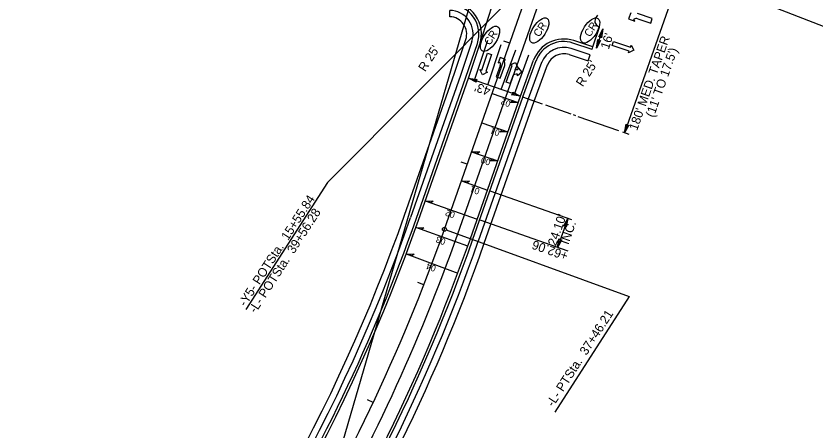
# Model space of a CAD drawing. Extents: x 1974386 to 1979988, y 776712 to 784860.
# Drawn here: x 1976973 to 1977598, y 780494 to 780818 of the extents above; entities that cross this region are included whole.
import ezdxf

# ---------------------------------------------------------------- set-up
doc = ezdxf.new("R2010")
doc.units = 0
for name, color, linetype in [('Prop Conc 2ft 6in Curb and Gutter', 7, 'Continuous'), ('Prop Conc 4in Sidewalk', 7, 'Continuous'), ('Prop Dimension', 7, 'Continuous'), ('Prop Dimension Text', 7, 'Continuous'), ('Prop EOT', 7, 'Continuous'), ('Prop Horizontal Alignment', 7, 'Continuous'), ('Prop Horizontal Alignment Station Label', 7, 'Continuous'), ('Prop Horizontal Alignment Tick Small', 7, 'Continuous'), ('Prop Lane Arrow CELL', 7, 'Continuous'), ('Prop Lane Lines', 7, 'Continuous'), ('Prop Superelevation  Arrow CELL', 7, 'Continuous'), ('Prop Superelevation Label', 7, 'Continuous'), ('Prop Terminator CELL', 7, 'Continuous'), ('Prop WCC CELL', 7, 'Continuous'), ('Scratch_Level_2', 7, 'Continuous'), ('Scratch_Level_3', 7, 'Continuous'), ('Sheet Layout Plan Border', 7, 'Continuous')]:
    doc.layers.add(name, color=color, linetype=linetype)

msp = doc.modelspace()

# ---------------------------------------------------------------- linework, layer by layer
at = {"layer": 'Prop Conc 2ft 6in Curb and Gutter'}
for p, q in [((1977423.02, 780791.58), (1977408.13, 780796.51)), ((1977324.63, 780769.91), (1977333.5, 780796.19)), ((1977423.02, 780791.58), (1977423.65, 780793.48)), ((1977369.03, 780754.48), (1977379.43, 780782.92)), ((1977285.65, 780659.07), (1977324.64, 780769.93)), ((1977329.99, 780643.48), (1977368.97, 780754.34))]:
    msp.add_line(p, q, dxfattribs=at)
for centre, radius, start, end in [((1977311.71, 780803.55), 23, 341.34263, 89.03553), ((1977400.9, 780774.68), 23, 71.68278, 159.91031), ((1975987.1, 781115.69), 1376.5, 328.18457, 340.62647), ((1975987.1, 781115.69), 1423.5, 326.24911, 340.62647)]:
    msp.add_arc(centre, radius, start, end, dxfattribs=at)
at = {"layer": 'Prop Conc 4in Sidewalk'}
for p, q in [((1977311.94, 780817.04), (1977312.02, 780822.04)), ((1977311.94, 780817.04), (1977311.98, 780819.54)), ((1977315.67, 780773.08), (1977324.5, 780799.23)), ((1977329.24, 780797.63), (1977320.36, 780771.35)), ((1977421.61, 780787.31), (1977406.72, 780792.24)), ((1977405.14, 780787.49), (1977420.04, 780782.56)), ((1977420.04, 780782.56), (1977421.61, 780787.31)), ((1977383.66, 780781.38), (1977373.24, 780752.91)), ((1977377.94, 780751.19), (1977388.35, 780779.66)), ((1977276.69, 780662.22), (1977315.67, 780773.08)), ((1977320.36, 780771.35), (1977281.41, 780660.56)), ((1977373.22, 780752.85), (1977334.24, 780641.98)), ((1977338.95, 780640.33), (1977377.94, 780751.19))]:
    msp.add_line(p, q, dxfattribs=at)
for centre, radius, start, end in [((1977311.71, 780803.55), 18.5, 341.34263, 89.03553), ((1977311.71, 780803.55), 13.5, 341.34263, 89.03553), ((1977400.9, 780774.68), 18.5, 71.68278, 159.91031), ((1977400.9, 780774.68), 13.5, 71.68278, 159.91031), ((1975987.1, 781115.69), 1367, 320.45193, 340.62647), ((1975987.1, 781115.69), 1372, 320.5086, 340.62647), ((1975987.1, 781115.69), 1428, 326.24911, 340.62647), ((1975987.1, 781115.69), 1433, 326.24911, 340.62647)]:
    msp.add_arc(centre, radius, start, end, dxfattribs=at)
at = {"layer": 'Prop Dimension'}
for p, q in [((1977508.17, 780896.2), (1977448.46, 780726.39)), ((1977426.51, 780792.53), (1977431.47, 780807.53)), ((1977367.09, 780755), (1977326.52, 780769.27)), ((1977384.39, 780748.92), (1977369.13, 780754.28)), ((1977406.69, 780741.08), (1977386.92, 780748.03)), ((1977410.43, 780739.76), (1977408.57, 780740.42)), ((1977443.97, 780727.97), (1977412.29, 780739.11)), ((1977451.87, 780725.19), (1977446.99, 780726.91)), ((1977407.19, 780658.68), (1977343.62, 780681.04)), ((1977404.05, 780659.79), (1977396.05, 780637.05)), ((1977404.49, 780634.09), (1977335.71, 780658.27))]:
    msp.add_line(p, q, dxfattribs=at)
at = {"layer": 'Prop EOT'}
for p, q in [((1977425.43, 780812.69), (1977425.62, 780815.57)), ((1977425.62, 780815.57), (1977427.56, 780818.27)), ((1977423.65, 780793.48), (1977428.77, 780808.93)), ((1977427.32, 780809.61), (1977425.43, 780812.69)), ((1977423.65, 780793.48), (1977408.76, 780798.41)), ((1977326.52, 780769.27), (1977335.4, 780795.55)), ((1977367.14, 780755.14), (1977377.42, 780783.26)), ((1977287.54, 780658.4), (1977326.52, 780769.27)), ((1977328.1, 780644.14), (1977367.09, 780755))]:
    msp.add_line(p, q, dxfattribs=at)
msp.add_lwpolyline([(1977428.77, 780808.93), (1977428.16, 780809.13), (1977427.32, 780809.61)], dxfattribs=at)
for centre, radius, start, end in [((1977311.71, 780803.55), 25, 341.34263, 89.03553), ((1977400.9, 780774.68), 25, 71.68278, 159.91031), ((1975987.1, 781115.69), 1378.5, 320.50095, 340.62647), ((1975987.1, 781115.69), 1421.5, 326.24911, 340.61773)]:
    msp.add_arc(centre, radius, start, end, dxfattribs=at)
at = {"layer": 'Prop Horizontal Alignment'}
msp.add_line((1977307.82, 780651.27), (1977457.11, 781075.82), dxfattribs=at)
msp.add_arc((1975987.1, 781115.69), 1400, 315.73946, 340.62647, dxfattribs=at)
at = {"layer": 'Prop Horizontal Alignment Station Label'}
for p, q in [((1977376.45, 780848.38), (1977216.45, 780687.69)), ((1977216.45, 780687.69), (1977152.74, 780588.6)), ((1977309.24, 780650.77), (1977451.88, 780598.87)), ((1977451.88, 780598.87), (1977393.85, 780508.64))]:
    msp.add_line(p, q, dxfattribs=at)
msp.add_circle((1977307.82, 780651.27), 1.5, dxfattribs=at)
at = {"layer": 'Prop Horizontal Alignment Tick Small'}
for p, q in [((1977358.84, 780796.36), (1977354.12, 780798.01)), ((1977325.67, 780702.02), (1977320.95, 780703.68)), ((1977291.78, 780607.94), (1977287.12, 780609.75)), ((1977252.21, 780516.12), (1977247.7, 780518.27))]:
    msp.add_line(p, q, dxfattribs=at)
at = {"layer": 'Prop Lane Arrow CELL'}
for p, q in [((1977453.25, 780820.12), (1977451.56, 780815.35)), ((1977451.56, 780815.35), (1977456.45, 780813.63)), ((1977456.45, 780813.63), (1977455.69, 780815.16)), ((1977470.02, 780815.7), (1977458.53, 780819.6)), ((1977458.84, 780815.49), (1977468.8, 780812.11)), ((1977468.8, 780812.11), (1977470.02, 780815.7)), ((1977438.76, 780794.66), (1977439.79, 780797.8)), ((1977439.79, 780797.8), (1977453.09, 780793.43)), ((1977452.06, 780790.3), (1977438.76, 780794.66)), ((1977455.58, 780790.93), (1977451.59, 780788.87)), ((1977451.59, 780788.87), (1977452.06, 780790.3)), ((1977453.09, 780793.43), (1977453.56, 780794.86)), ((1977453.56, 780794.86), (1977455.58, 780790.93)), ((1977336.96, 780775.35), (1977341.48, 780788.6)), ((1977344.61, 780787.54), (1977340.09, 780774.29)), ((1977341.48, 780788.6), (1977344.61, 780787.54)), ((1977351.29, 780785.21), (1977349.72, 780780.99)), ((1977355.41, 780783.68), (1977351.29, 780785.21)), ((1977351.31, 780778.89), (1977348.22, 780770.27)), ((1977349.72, 780780.99), (1977351.07, 780781.63)), ((1977351.33, 780769.16), (1977354.88, 780779.09)), ((1977354.07, 780783.05), (1977355.41, 780783.68)), ((1977356.06, 780766.05), (1977360.62, 780779.08)), ((1977359.2, 780779.57), (1977363.2, 780781.46)), ((1977360.62, 780779.08), (1977359.2, 780779.57)), ((1977363.73, 780777.99), (1977362.79, 780775.3)), ((1977363.2, 780781.46), (1977365.15, 780777.49)), ((1977365.15, 780777.49), (1977363.73, 780777.99)), ((1977337.55, 780771.82), (1977335.54, 780775.84)), ((1977335.54, 780775.84), (1977336.96, 780775.35)), ((1977341.5, 780773.8), (1977337.55, 780771.82)), ((1977340.09, 780774.29), (1977341.5, 780773.8)), ((1977368.15, 780773.8), (1977364.8, 780770.89)), ((1977364.8, 780770.89), (1977364.88, 780772.34)), ((1977365.14, 780775.64), (1977365.24, 780777.14)), ((1977365.24, 780777.14), (1977368.15, 780773.8)), ((1977348.22, 780770.27), (1977351.33, 780769.16)), ((1977359.18, 780764.96), (1977356.06, 780766.05)), ((1977361.31, 780771.05), (1977359.18, 780764.96))]:
    msp.add_line(p, q, dxfattribs=at)
for centre, radius, start, end in [((1977457.62, 780811.95), 3.77, 71.25132, 120.90949), ((1977348.24, 780780), 3.27, 340.30395, 29.96213), ((1977349.74, 780780.09), 5.25, 348.98002, 34.29172), ((1977363.4, 780769.64), 2.52, 109.80631, 146.11831), ((1977364.3, 780767.94), 4.43, 82.44284, 113.2964), ((1977364.54, 780771.24), 4.43, 82.32403, 113.20263)]:
    msp.add_arc(centre, radius, start, end, dxfattribs=at)
at = {"layer": 'Prop Lane Lines'}
for p, q in [((1977331.24, 780767.62), (1977341.8, 780798.87)), ((1977341.62, 780763.96), (1977352.01, 780795.31)), ((1977351.99, 780760.31), (1977363.47, 780791.16)), ((1977362.38, 780756.67), (1977373.63, 780787.45))]:
    msp.add_line(p, q, dxfattribs=at)
at = {"layer": 'Prop Superelevation  Arrow CELL'}
for p, q in [((1977345.06, 780757.17), (1977365.34, 780750.04)), ((1977337.06, 780734.43), (1977357.35, 780727.3)), ((1977329.07, 780711.7), (1977349.35, 780704.57)), ((1977321.08, 780688.96), (1977341.36, 780681.83)), ((1977292.8, 780673.36), (1977333.36, 780659.09)), ((1977325.98, 780638.15), (1977285.48, 780652.6)), ((1977278, 780632.14), (1977318.27, 780617.06))]:
    msp.add_line(p, q, dxfattribs=at)
for points in [[(1977365.34, 780750.04), (1977359.02, 780750.14), (1977360.98, 780751.57)], [(1977357.35, 780727.3), (1977351.02, 780727.4), (1977352.98, 780728.83)], [(1977329.07, 780711.7), (1977335.39, 780711.59), (1977333.43, 780710.16)], [(1977349.35, 780704.57), (1977343.03, 780704.67), (1977344.99, 780706.1)], [(1977321.08, 780688.96), (1977327.4, 780688.86), (1977325.44, 780687.43)], [(1977292.8, 780673.36), (1977299.12, 780673.25), (1977297.16, 780671.82)], [(1977285.48, 780652.6), (1977291.81, 780652.46), (1977289.84, 780651.04)], [(1977278, 780632.14), (1977284.32, 780631.91), (1977282.34, 780630.52)]]:
    msp.add_lwpolyline(points, close=True, dxfattribs=at)
at = {"layer": 'Prop Terminator CELL'}
for points in [[(1977428.25, 780801.48), (1977431.47, 780807.53), (1977430.48, 780800.71), (1977429.61, 780801.9)], [(1977429.73, 780798.58), (1977426.51, 780792.53), (1977427.5, 780799.35), (1977428.37, 780798.16)], [(1977332.5, 780765.93), (1977326.52, 780769.27), (1977333.32, 780768.15), (1977332.11, 780767.3)], [(1977361.1, 780758.34), (1977367.09, 780755), (1977360.29, 780756.12), (1977361.5, 780756.97)], [(1977451.79, 780732.37), (1977448.46, 780726.39), (1977449.58, 780733.19), (1977450.42, 780731.98)], [(1977400.71, 780653.8), (1977404.05, 780659.79), (1977402.93, 780652.98), (1977402.08, 780654.2)], [(1977399.39, 780643.03), (1977396.05, 780637.05), (1977397.17, 780643.85), (1977398.02, 780642.64)]]:
    msp.add_lwpolyline(points, close=True, dxfattribs=at)
at = {"layer": 'Prop WCC CELL'}
for centre in [(1977381.84, 780806.3), (1977421.51, 780806.35), (1977343.38, 780799.87)]:
    msp.add_ellipse(centre, major_axis=(6.07, 9.43), ratio=0.462467, dxfattribs=at)
at = {"layer": 'Scratch_Level_2'}
for p, q in [((1977203.85, 780401.24), (1977333.59, 780846.18)), ((1977318.2, 780647.62), (1977387.7, 780845.27))]:
    msp.add_line(p, q, dxfattribs=at)
msp.add_arc((1975987.1, 781115.69), 1411, 329.5795, 340.62647, dxfattribs=at)
at = {"layer": 'Scratch_Level_3'}
msp.add_line((1977335.4, 780795.55), (1977368.28, 780897.82), dxfattribs=at)
at = {"layer": 'Sheet Layout Plan Border'}
msp.add_lwpolyline([(1977881.86, 780701.89), (1978387.67, 782007.32), (1977408.59, 782386.68), (1976902.78, 781081.25)], close=True, dxfattribs=at)

# ---------------------------------------------------------------- texts
at = {"layer": 'Prop Dimension Text'}
for s, rotation, p in [("16'", 71.68278, (1977436.02, 780791.16)), ("180' MED. TAPER ", 70.62647, (1977458.16, 780727.76)), ("R 25'", 57.25495, (1977292.78, 780773.69)), ("  (11' TO 17.5')", 70.62647, (1977469.45, 780733.14)), ("R 25'", 57.25495, (1977415.8, 780761.94)), ("43'", 160.62647, (1977344.47, 780761.78)), ("24.10'", 70.62647, (1977394.8, 780637.83)), ('INC.', 70.62647, (1977404.55, 780638.79)), ('+62.06', 160.62647, (1977404.98, 780633.29))]:
    msp.add_text(s, height=7, rotation=rotation, dxfattribs=at).set_placement(p)
at = {"layer": 'Prop Horizontal Alignment Station Label'}
for s, rotation, p in [('-Y5- POTSta.  15+55.84', 57.18503, (1977152.49, 780590.48)), ('-L- POTSta.  39+56.28', 57.18503, (1977160.46, 780585.36)), ('-L- PTSta.  37+46.21', 57.18801, (1977392.74, 780512.28))]:
    msp.add_text(s, height=7, rotation=rotation, dxfattribs=at).set_placement(p)
at = {"layer": 'Prop Superelevation Label'}
for s, rotation, p in [('02', 160.62647, (1977359.96, 780751.1)), ('01', 160.62647, (1977351.57, 780728.46)), ('00', 160.62647, (1977344.37, 780705.52)), ('01', 160.62647, (1977335.81, 780682.86)), ('02', 160.62647, (1977316.55, 780664.36)), ('03', 160.37034, (1977309.27, 780643.47)), ('04', 159.46506, (1977301.72, 780622.61))]:
    msp.add_text(s, height=5, rotation=rotation, dxfattribs=at).set_placement(p)
at = {"layer": 'Prop WCC CELL'}
for p in [(1977381.78, 780800.74), (1977421.44, 780800.78), (1977343.31, 780794.3)]:
    msp.add_text('CR', height=6, rotation=57.25497, dxfattribs=at).set_placement(p)

doc.saveas('drawing.dxf')
